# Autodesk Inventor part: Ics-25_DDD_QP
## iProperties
Created: 2007-02
Part Number: Ics-25_DDD_QP
Checked By: Alves
Material: nicht zugewiesen
Description: XX BENENNUNG XX
Document SubType Name: Modellieren
Designer: Klein
ME: ST
Title: XX Gruppe XX
Author: Klein
Comments: keine Bemerkung
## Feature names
1. Grundkörper [Extrusion]
2. Grundkörperkontur [Extrusion]
3. Vertiefung [Extrusion]
4. 3 LED Fenster [Extrusion]
5. Sensoraufnahme [Extrusion]
6. Extrusion6
7. Drehung2 [Revolution]
8. Extrusion7
9. Rundung1 [Fillet]
10. Extrusion8
11. Extrusion9
12. Rundung2 [Fillet]
13. Drehung1 [Revolution]
